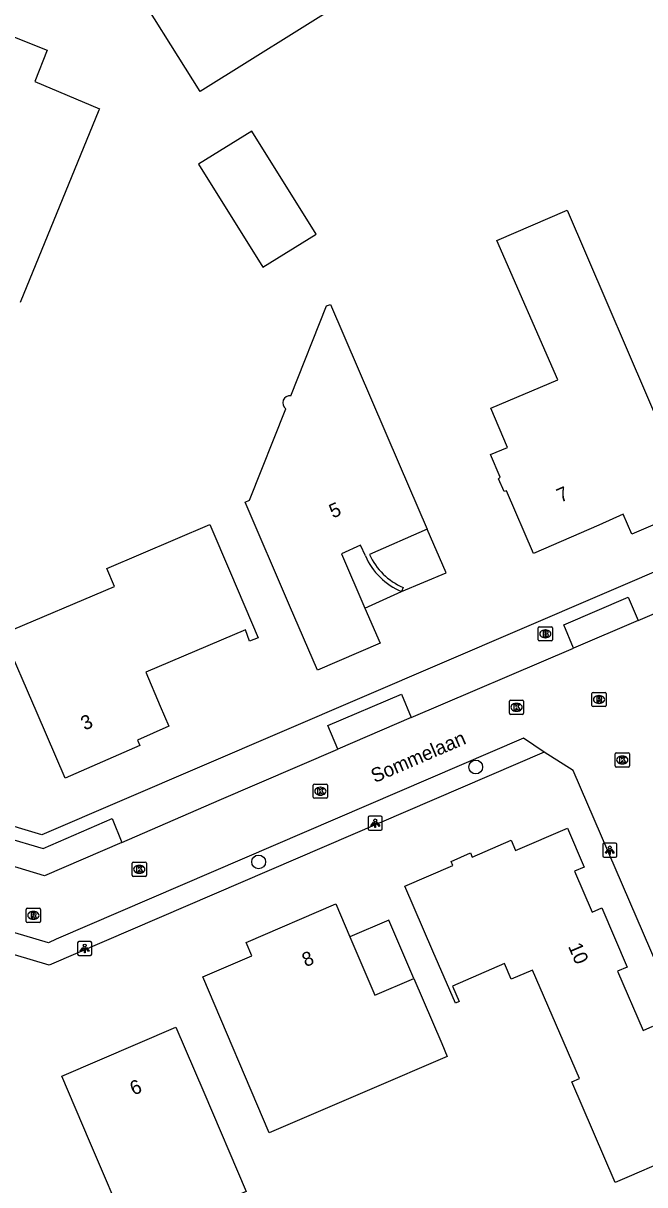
# Model space of a CAD drawing. Extents: x 157767 to 159171, y 387842 to 389425.
# Drawn here: x 158095.4 to 158139.4, y 388753.5 to 388835.7 of the extents above; entities that cross this region are included whole.
import ezdxf

# ---------------------------------------------------------------- set-up
doc = ezdxf.new("R2010")
doc.units = 0
for name, color, linetype in [('IMGEO_Boom', 7, 'Continuous'), ('IMGEO_Brandkraan', 7, 'Continuous'), ('IMGEO_Kolk', 7, 'Continuous'), ('IMGEO_Lichtpunt', 7, 'Continuous'), ('IMGEO_Openbare_ruimte_label', 7, 'Continuous'), ('IMGEO_Pand', 7, 'Continuous'), ('IMGEO_Pand_nummerreeks', 7, 'Continuous'), ('IMGEO_Pand_overbouw', 7, 'Continuous'), ('IMGEO_Rijbaan_lokaal_open', 7, 'Continuous'), ('IMGEO_Rioolput', 7, 'Continuous'), ('IMGEO_Voetpad_open', 7, 'Continuous')]:
    doc.layers.add(name, color=color, linetype=linetype)

msp = doc.modelspace()

# ---------------------------------------------------------------- linework, layer by layer
at = {"layer": 'IMGEO_Boom'}
for centre in [(158127.417, 388783.049), (158112.044, 388776.326)]:
    msp.add_circle(centre, 0.489, dxfattribs=at)
at = {"layer": 'IMGEO_Brandkraan'}
for p, q in [((158131.848, 388792.054), (158131.848, 388792.906)), ((158131.923, 388792.98), (158132.775, 388792.98)), ((158132.336, 388792.76), (158132.361, 388792.76)), ((158132.849, 388792.906), (158132.849, 388792.054)), ((158132.775, 388791.98), (158131.923, 388791.98)), ((158132.359, 388792.2), (158132.334, 388792.2))]:
    msp.add_line(p, q, dxfattribs=at)
for points in [[(158131.848, 388792.054), (158131.848, 388792.906)], [(158131.923, 388792.98), (158132.775, 388792.98)], [(158132.849, 388792.906), (158132.849, 388792.054)], [(158132.775, 388791.98), (158131.923, 388791.98)], [(158132.196, 388792.68), (158132.196, 388792.28), (158132.409, 388792.28)], [(158132.427, 388792.68), (158132.196, 388792.68)], [(158132.375, 388792.599), (158132.321, 388792.599), (158132.321, 388792.523)], [(158132.321, 388792.523), (158132.374, 388792.523)], [(158132.383, 388792.447), (158132.321, 388792.447), (158132.321, 388792.366)], [(158132.321, 388792.366), (158132.383, 388792.366)]]:
    msp.add_lwpolyline(points, dxfattribs=at)
for centre, radius, start, end in [((158131.925, 388792.904), 0.0765, 91.55205, 178.44795), ((158131.925, 388792.904), 0.0765, 91.55205, 178.44795), ((158132.773, 388792.904), 0.0765, 1.55205, 88.44795), ((158132.773, 388792.904), 0.0765, 1.55205, 88.44795), ((158131.925, 388792.056), 0.0765, 181.55205, 268.44795), ((158131.925, 388792.056), 0.0765, 181.55205, 268.44795), ((158132.376, 388792.561), 0.0379, 267.82845, 90.93552), ((158132.384, 388792.406), 0.0404, 269.87594, 90.50774), ((158132.415, 388792.531), 0.251, 268.66757, 293.53466), ((158132.431, 388792.535), 0.145, 59.4692, 91.53667), ((158132.456, 388792.582), 0.0922, 285.51372, 58.15012), ((158132.461, 388792.39), 0.105, 301.31148, 78.98903), ((158132.773, 388792.056), 0.0765, 271.55205, 358.44795), ((158132.773, 388792.056), 0.0765, 271.55205, 358.44795)]:
    msp.add_arc(centre, radius, start, end, dxfattribs=at)
for centre, major_axis, ratio, start_param, end_param in [((158132.335, 388792.48), (-0.387, 0.002), 0.722429, 4.712389, 7.853982), ((158132.36, 388792.48), (-0.39, 0.002), 0.717154, 1.570796, 4.712389)]:
    msp.add_ellipse(centre, major_axis=major_axis, ratio=ratio, start_param=start_param, end_param=end_param, dxfattribs=at)
at = {"layer": 'IMGEO_Kolk'}
for p, q in [((158129.81, 388786.853), (158129.81, 388787.705)), ((158129.885, 388787.779), (158130.737, 388787.779)), ((158130.321, 388786.999), (158130.296, 388786.999)), ((158130.298, 388787.559), (158130.323, 388787.559)), ((158130.811, 388787.705), (158130.811, 388786.853)), ((158130.737, 388786.779), (158129.885, 388786.779)), ((158137.3, 388783.122), (158137.3, 388783.974)), ((158137.375, 388784.048), (158138.227, 388784.048)), ((158137.788, 388783.828), (158137.813, 388783.828)), ((158138.301, 388783.974), (158138.301, 388783.122)), ((158138.227, 388783.048), (158137.375, 388783.048)), ((158137.811, 388783.268), (158137.786, 388783.268)), ((158115.916, 388780.91), (158115.916, 388781.762)), ((158115.991, 388781.836), (158116.843, 388781.836)), ((158116.404, 388781.616), (158116.429, 388781.616)), ((158116.917, 388781.762), (158116.917, 388780.91)), ((158116.843, 388780.836), (158115.991, 388780.836)), ((158116.427, 388781.056), (158116.402, 388781.056)), ((158103.166, 388776.305), (158104.018, 388776.305)), ((158103.091, 388775.379), (158103.091, 388776.231)), ((158103.602, 388775.525), (158103.577, 388775.525)), ((158103.579, 388776.085), (158103.604, 388776.085)), ((158104.092, 388776.231), (158104.092, 388775.379)), ((158104.018, 388775.305), (158103.166, 388775.305))]:
    msp.add_line(p, q, dxfattribs=at)
for points in [[(158129.81, 388786.853), (158129.81, 388787.705)], [(158129.885, 388787.779), (158130.737, 388787.779)], [(158130.131, 388787.479), (158130.254, 388787.479), (158130.254, 388787.328), (158130.384, 388787.479), (158130.548, 388787.479), (158130.402, 388787.328), (158130.555, 388787.079), (158130.403, 388787.079), (158130.318, 388787.243), (158130.254, 388787.176), (158130.254, 388787.079), (158130.131, 388787.079), (158130.131, 388787.479)], [(158130.811, 388787.705), (158130.811, 388786.853)], [(158130.737, 388786.779), (158129.885, 388786.779)], [(158137.3, 388783.122), (158137.3, 388783.974)], [(158137.375, 388784.048), (158138.227, 388784.048)], [(158137.621, 388783.748), (158137.744, 388783.748), (158137.744, 388783.597), (158137.874, 388783.748), (158138.038, 388783.748), (158137.892, 388783.597), (158138.045, 388783.348), (158137.893, 388783.348), (158137.808, 388783.512), (158137.744, 388783.445), (158137.744, 388783.348), (158137.621, 388783.348), (158137.621, 388783.748)], [(158138.301, 388783.974), (158138.301, 388783.122)], [(158138.227, 388783.048), (158137.375, 388783.048)], [(158115.916, 388780.91), (158115.916, 388781.762)], [(158115.991, 388781.836), (158116.843, 388781.836)], [(158116.237, 388781.536), (158116.36, 388781.536), (158116.36, 388781.385), (158116.49, 388781.536), (158116.654, 388781.536), (158116.508, 388781.385), (158116.661, 388781.136), (158116.509, 388781.136), (158116.424, 388781.3), (158116.36, 388781.233), (158116.36, 388781.136), (158116.237, 388781.136), (158116.237, 388781.536)], [(158116.917, 388781.762), (158116.917, 388780.91)], [(158116.843, 388780.836), (158115.991, 388780.836)], [(158103.166, 388776.305), (158104.018, 388776.305)], [(158103.091, 388775.379), (158103.091, 388776.231)], [(158103.412, 388776.005), (158103.535, 388776.005), (158103.535, 388775.854), (158103.665, 388776.005), (158103.829, 388776.005), (158103.683, 388775.854), (158103.836, 388775.605), (158103.684, 388775.605), (158103.599, 388775.769), (158103.535, 388775.702), (158103.535, 388775.605), (158103.412, 388775.605), (158103.412, 388776.005)], [(158104.092, 388776.231), (158104.092, 388775.379)], [(158104.018, 388775.305), (158103.166, 388775.305)]]:
    msp.add_lwpolyline(points, dxfattribs=at)
for centre, start, end in [((158129.887, 388787.703), 91.55205, 178.44795), ((158129.887, 388787.703), 91.55205, 178.44795), ((158130.735, 388787.703), 1.55205, 88.44795), ((158130.735, 388787.703), 1.55205, 88.44795), ((158129.887, 388786.855), 181.55205, 268.44795), ((158129.887, 388786.855), 181.55205, 268.44795), ((158130.735, 388786.855), 271.55205, 358.44795), ((158130.735, 388786.855), 271.55205, 358.44795), ((158137.377, 388783.972), 91.55205, 178.44795), ((158137.377, 388783.972), 91.55205, 178.44795), ((158138.225, 388783.972), 1.55205, 88.44795), ((158138.225, 388783.972), 1.55205, 88.44795), ((158137.377, 388783.124), 181.55205, 268.44795), ((158137.377, 388783.124), 181.55205, 268.44795), ((158138.225, 388783.124), 271.55205, 358.44795), ((158138.225, 388783.124), 271.55205, 358.44795), ((158115.993, 388781.76), 91.55205, 178.44795), ((158115.993, 388781.76), 91.55205, 178.44795), ((158116.841, 388781.76), 1.55205, 88.44795), ((158116.841, 388781.76), 1.55205, 88.44795), ((158115.993, 388780.912), 181.55205, 268.44795), ((158115.993, 388780.912), 181.55205, 268.44795), ((158116.841, 388780.912), 271.55205, 358.44795), ((158116.841, 388780.912), 271.55205, 358.44795), ((158103.168, 388776.229), 91.55205, 178.44795), ((158103.168, 388776.229), 91.55205, 178.44795), ((158104.016, 388776.229), 1.55205, 88.44795), ((158104.016, 388776.229), 1.55205, 88.44795), ((158103.168, 388775.381), 181.55205, 268.44795), ((158103.168, 388775.381), 181.55205, 268.44795), ((158104.016, 388775.381), 271.55205, 358.44795), ((158104.016, 388775.381), 271.55205, 358.44795)]:
    msp.add_arc(centre, 0.0765, start, end, dxfattribs=at)
for centre, major_axis, ratio, start_param, end_param in [((158130.297, 388787.279), (-0.387, 0.002), 0.722429, 4.712389, 7.853982), ((158130.322, 388787.279), (-0.39, 0.002), 0.717154, 1.570796, 4.712389), ((158137.787, 388783.548), (-0.387, 0.002), 0.722429, 4.712389, 7.853982), ((158137.812, 388783.548), (-0.39, 0.002), 0.717154, 1.570796, 4.712389), ((158116.403, 388781.336), (-0.387, 0.002), 0.722429, 4.712389, 7.853982), ((158116.428, 388781.336), (-0.39, 0.002), 0.717154, 1.570796, 4.712389), ((158103.578, 388775.805), (-0.387, 0.002), 0.722429, 4.712389, 7.853982), ((158103.603, 388775.805), (-0.39, 0.002), 0.717154, 1.570796, 4.712389)]:
    msp.add_ellipse(centre, major_axis=major_axis, ratio=ratio, start_param=start_param, end_param=end_param, dxfattribs=at)
at = {"layer": 'IMGEO_Lichtpunt'}
for p, q in [((158120.707, 388779.569), (158119.899, 388779.569)), ((158120.707, 388779.569), (158119.899, 388779.569)), ((158119.805, 388779.474), (158119.805, 388778.667)), ((158119.805, 388779.474), (158119.805, 388778.667)), ((158120.801, 388778.667), (158120.801, 388779.474)), ((158120.801, 388778.667), (158120.801, 388779.474)), ((158119.899, 388778.573), (158120.707, 388778.573)), ((158119.899, 388778.573), (158120.707, 388778.573)), ((158136.414, 388777.561), (158136.414, 388776.754)), ((158136.414, 388777.561), (158136.414, 388776.754)), ((158137.316, 388777.656), (158136.508, 388777.656)), ((158137.316, 388777.656), (158136.508, 388777.656)), ((158137.41, 388776.754), (158137.41, 388777.561)), ((158137.41, 388776.754), (158137.41, 388777.561)), ((158136.508, 388776.66), (158137.316, 388776.66)), ((158136.508, 388776.66), (158137.316, 388776.66)), ((158099.224, 388770.601), (158099.224, 388769.794)), ((158099.224, 388770.601), (158099.224, 388769.794)), ((158100.126, 388770.696), (158099.318, 388770.696)), ((158100.126, 388770.696), (158099.318, 388770.696)), ((158100.22, 388769.794), (158100.22, 388770.601)), ((158100.22, 388769.794), (158100.22, 388770.601)), ((158099.318, 388769.7), (158100.126, 388769.7)), ((158099.318, 388769.7), (158100.126, 388769.7))]:
    msp.add_line(p, q, dxfattribs=at)
for points in [[(158120.179, 388779.138), (158120.218, 388779.11), (158120.03, 388778.848), (158119.992, 388778.875), (158120.179, 388779.138)], [(158120.281, 388779.09), (158120.328, 388779.09), (158120.328, 388778.768), (158120.281, 388778.768), (158120.281, 388779.09)], [(158120.391, 388779.11), (158120.429, 388779.137), (158120.616, 388778.875), (158120.577, 388778.847), (158120.391, 388779.11)], [(158136.788, 388777.225), (158136.827, 388777.197), (158136.639, 388776.935), (158136.601, 388776.962), (158136.788, 388777.225)], [(158136.89, 388777.177), (158136.937, 388777.177), (158136.937, 388776.855), (158136.89, 388776.855), (158136.89, 388777.177)], [(158137, 388777.197), (158137.038, 388777.224), (158137.225, 388776.962), (158137.186, 388776.934), (158137, 388777.197)], [(158099.598, 388770.265), (158099.637, 388770.237), (158099.449, 388769.975), (158099.411, 388770.002), (158099.598, 388770.265)], [(158099.7, 388770.217), (158099.747, 388770.217), (158099.747, 388769.895), (158099.7, 388769.895), (158099.7, 388770.217)], [(158099.81, 388770.237), (158099.848, 388770.264), (158100.035, 388770.002), (158099.996, 388769.974), (158099.81, 388770.237)]]:
    msp.add_lwpolyline(points, dxfattribs=at)
for centre in [(158120.304, 388779.272), (158136.913, 388777.359), (158099.723, 388770.399)]:
    msp.add_circle(centre, 0.0994, dxfattribs=at)
for centre, start, end in [((158119.899, 388779.474), 90, 180), ((158119.899, 388779.474), 90, 180), ((158120.707, 388779.474), 0, 90), ((158120.707, 388779.474), 0, 90), ((158119.899, 388778.667), 180, 270), ((158119.899, 388778.667), 180, 270), ((158120.707, 388778.667), 270, 0), ((158120.707, 388778.667), 270, 360), ((158136.508, 388777.561), 90, 180), ((158136.508, 388777.561), 90, 180), ((158137.316, 388777.561), 0, 90), ((158137.316, 388777.561), 0, 90), ((158136.508, 388776.754), 180, 270), ((158136.508, 388776.754), 180, 270), ((158137.316, 388776.754), 270, 0), ((158137.316, 388776.754), 270, 360), ((158099.318, 388770.601), 90, 180), ((158099.318, 388770.601), 90, 180), ((158100.126, 388770.601), 0, 90), ((158100.126, 388770.601), 0, 90), ((158099.318, 388769.794), 180, 270), ((158099.318, 388769.794), 180, 270), ((158100.126, 388769.794), 270, 0), ((158100.126, 388769.794), 270, 360)]:
    msp.add_arc(centre, 0.0946, start, end, dxfattribs=at)
at = {"layer": 'IMGEO_Pand'}
for points in [[(158107.9, 388830.88), (158102.6, 388839.361), (158099.95, 388843.6), (158104.286, 388846.313), (158104.628, 388845.765), (158106.324, 388846.828), (158105.97, 388847.367), (158110.29, 388850.07), (158112.945, 388845.833), (158118.26, 388837.349), (158107.9, 388830.88)], [(158090.94, 388832.057), (158092.413, 388835.668), (158097.058, 388833.817), (158096.185, 388831.597), (158100.769, 388829.656), (158100.729, 388829.559), (158095.153, 388815.955)], [(158107.791, 388825.731), (158112.347, 388818.441), (158116.114, 388820.795), (158111.558, 388828.085), (158107.791, 388825.731)], [(158133.899, 388822.494), (158140.955, 388806.047), (158142.926, 388801.451), (158138.474, 388799.53), (158137.864, 388800.944), (158136.133, 388800.188), (158131.502, 388798.164), (158129.587, 388802.604), (158129.432, 388802.561), (158129.037, 388803.465), (158129.142, 388803.58), (158128.469, 388805.175), (158129.667, 388805.684), (158128.486, 388808.465), (158133.228, 388810.479), (158128.925, 388820.345), (158133.899, 388822.494)], [(158114.326, 388809.33), (158116.857, 388815.698), (158117.129, 388815.797), (158122.003, 388804.491)], [(158119.603, 388797.997), (158119.263, 388798.752), (158117.903, 388798.148), (158119.569, 388794.299), (158120.642, 388791.821), (158116.209, 388789.896), (158114.234, 388794.49), (158111.093, 388801.795), (158111.389, 388801.957), (158113.969, 388808.421)], [(158122.003, 388804.491), (158123.983, 388799.899), (158119.901, 388798.11)], [(158112.009, 388792.192), (158111.402, 388791.962), (158111.102, 388792.762), (158104.047, 388789.771), (158105.08, 388787.353), (158105.683, 388785.942), (158103.459, 388784.961), (158103.62, 388784.578), (158098.336, 388782.268), (158096.353, 388786.858), (158093.926, 388792.476), (158101.828, 388795.84), (158101.291, 388797.104), (158108.593, 388800.213), (158110.05, 388796.793), (158112.009, 388792.192)], [(158122.274, 388795.764), (158122.168, 388795.47)], [(158124.388, 388770.019), (158122.403, 388774.608), (158125.802, 388776.074), (158125.676, 388776.368), (158127.043, 388776.961), (158127.17, 388776.668), (158129.923, 388777.86), (158130.241, 388777.127), (158133.91, 388778.716), (158135.096, 388775.965), (158134.408, 388775.669), (158135.654, 388772.776), (158136.342, 388773.072), (158138.148, 388768.88), (158137.461, 388768.583), (158139.269, 388764.39), (158139.953, 388764.685)], [(158119.894, 388760.181), (158112.797, 388757.131), (158108.08, 388768.184), (158111.563, 388769.67), (158111.158, 388770.62), (158117.502, 388773.351), (158118.506, 388771.013), (158120.279, 388766.885), (158123.034, 388768.068), (158125.008, 388763.474), (158125.405, 388762.549), (158119.894, 388760.181)], [(158142.873, 388756.025), (158138.284, 388754.042), (158137.304, 388753.618), (158134.219, 388760.754), (158134.76, 388760.988), (158131.438, 388768.674), (158129.935, 388768.024), (158129.459, 388769.127), (158125.779, 388767.536), (158126.255, 388766.434), (158125.988, 388766.318), (158124.388, 388770.019)], [(158102.873, 388750), (158100.069, 388756.563), (158098.104, 388761.16), (158106.19, 388764.627), (158108.155, 388760.03), (158111.161, 388752.999), (158104.146, 388750), (158103.07, 388749.54), (158102.873, 388750)]]:
    msp.add_lwpolyline(points, dxfattribs=at)
for centre, radius, start, end in [((158114.253, 388808.834), 0.501, 81.58702, 235.52921), ((158124.06, 388799.956), 4.869, 203.72685, 247.1283), ((158124.069, 388799.952), 4.557, 203.84964, 246.806)]:
    msp.add_arc(centre, radius, start, end, dxfattribs=at)
at = {"layer": 'IMGEO_Pand_overbouw'}
for points in [[(158122.168, 388795.47), (158125.323, 388796.79), (158123.983, 388799.899), (158119.901, 388798.11)], [(158119.603, 388797.997), (158119.263, 388798.752), (158117.903, 388798.148), (158119.569, 388794.299)], [(158119.569, 388794.299), (158122.168, 388795.47)], [(158122.274, 388795.764), (158122.168, 388795.47)]]:
    msp.add_lwpolyline(points, dxfattribs=at)
msp.add_lwpolyline([(158123.034, 388768.068), (158121.261, 388772.197), (158118.506, 388771.013), (158120.279, 388766.885)], close=True, dxfattribs=at)
for centre, radius, start, end in [((158124.06, 388799.956), 4.869, 203.72685, 247.1283), ((158124.069, 388799.952), 4.557, 203.84964, 246.806)]:
    msp.add_arc(centre, radius, start, end, dxfattribs=at)
at = {"layer": 'IMGEO_Rijbaan_lokaal_open'}
for points in [[(158138.917, 388793.421), (158149.891, 388798.147)], [(158138.917, 388793.421), (158134.35, 388791.467)], [(158122.856, 388786.566), (158134.35, 388791.467)], [(158122.856, 388786.566), (158117.651, 388784.313)], [(158132.266, 388784.089), (158130.812, 388785.098), (158097.692, 388770.854), (158097.152, 388770.606), (158071.312, 388778.281)], [(158102.35, 388777.71), (158109.251, 388780.697), (158117.651, 388784.313)], [(158155.532, 388728.793), (158156.474, 388731.409), (158148.476, 388750), (158147.334, 388752.654), (158134.314, 388782.791), (158132.266, 388784.089)], [(158102.35, 388777.71), (158096.873, 388775.34), (158090.794, 388777.174)]]:
    msp.add_lwpolyline(points, dxfattribs=at)
at = {"layer": 'IMGEO_Rioolput'}
for p, q in [((158135.652, 388787.404), (158135.652, 388788.256)), ((158135.727, 388788.33), (158136.579, 388788.33)), ((158136.14, 388788.11), (158136.165, 388788.11)), ((158136.653, 388788.256), (158136.653, 388787.404)), ((158136.579, 388787.33), (158135.727, 388787.33)), ((158136.163, 388787.55), (158136.138, 388787.55)), ((158095.663, 388773.044), (158096.515, 388773.044)), ((158095.588, 388772.118), (158095.588, 388772.97)), ((158096.099, 388772.264), (158096.074, 388772.264)), ((158096.076, 388772.824), (158096.101, 388772.824)), ((158096.589, 388772.97), (158096.589, 388772.118)), ((158096.515, 388772.044), (158095.663, 388772.044))]:
    msp.add_line(p, q, dxfattribs=at)
for points in [[(158135.652, 388787.404), (158135.652, 388788.256)], [(158135.727, 388788.33), (158136.579, 388788.33)], [(158136.241, 388788.028), (158135.989, 388788.03), (158135.989, 388787.63)], [(158135.989, 388787.63), (158136.113, 388787.63), (158136.113, 388787.792), (158136.124, 388787.792)], [(158136.167, 388787.949), (158136.113, 388787.949), (158136.113, 388787.868)], [(158136.113, 388787.868), (158136.165, 388787.868)], [(158136.653, 388788.256), (158136.653, 388787.404)], [(158136.579, 388787.33), (158135.727, 388787.33)], [(158136.171, 388787.763), (158136.242, 388787.63), (158136.382, 388787.63), (158136.317, 388787.756)], [(158095.663, 388773.044), (158096.515, 388773.044)], [(158095.588, 388772.118), (158095.588, 388772.97)], [(158096.177, 388772.742), (158095.925, 388772.744), (158095.925, 388772.344)], [(158095.925, 388772.344), (158096.049, 388772.344), (158096.049, 388772.506), (158096.06, 388772.506)], [(158096.103, 388772.663), (158096.049, 388772.663), (158096.049, 388772.582)], [(158096.049, 388772.582), (158096.101, 388772.582)], [(158096.107, 388772.477), (158096.178, 388772.344), (158096.318, 388772.344), (158096.253, 388772.47)], [(158096.589, 388772.97), (158096.589, 388772.118)], [(158096.515, 388772.044), (158095.663, 388772.044)]]:
    msp.add_lwpolyline(points, dxfattribs=at)
for centre, radius, start, end in [((158135.729, 388788.254), 0.0765, 91.55205, 178.44795), ((158135.729, 388788.254), 0.0765, 91.55205, 178.44795), ((158136.123, 388787.739), 0.0533, 26.02933, 88.69889), ((158136.149, 388788.057), 0.19, 274.7715, 282.96867), ((158136.173, 388787.853), 0.0964, 77.00612, 93.18647), ((158136.187, 388787.91), 0.0378, 276.66336, 79.67722), ((158136.24, 388787.918), 0.109, 350.36119, 89.41601), ((158136.238, 388787.918), 0.112, 277.58423, 350.98172), ((158136.222, 388787.703), 0.108, 29.51342, 73.79051), ((158136.577, 388788.254), 0.0765, 1.55205, 88.44795), ((158136.577, 388788.254), 0.0765, 1.55205, 88.44795), ((158135.729, 388787.406), 0.0765, 181.55205, 268.44795), ((158135.729, 388787.406), 0.0765, 181.55205, 268.44795), ((158136.577, 388787.406), 0.0765, 271.55205, 358.44795), ((158136.577, 388787.406), 0.0765, 271.55205, 358.44795), ((158095.665, 388772.968), 0.0765, 91.55205, 178.44795), ((158095.665, 388772.968), 0.0765, 91.55205, 178.44795), ((158096.513, 388772.968), 0.0765, 1.55205, 88.44795), ((158096.513, 388772.968), 0.0765, 1.55205, 88.44795), ((158096.059, 388772.453), 0.0533, 26.02933, 88.69889), ((158096.085, 388772.771), 0.19, 274.7715, 282.96867), ((158096.109, 388772.567), 0.0964, 77.00612, 93.18647), ((158096.123, 388772.624), 0.0378, 276.66336, 79.67722), ((158096.176, 388772.632), 0.109, 350.36119, 89.41601), ((158096.174, 388772.632), 0.112, 277.58423, 350.98172), ((158096.158, 388772.417), 0.108, 29.51342, 73.79051), ((158095.665, 388772.12), 0.0765, 181.55205, 268.44795), ((158095.665, 388772.12), 0.0765, 181.55205, 268.44795), ((158096.513, 388772.12), 0.0765, 271.55205, 358.44795), ((158096.513, 388772.12), 0.0765, 271.55205, 358.44795)]:
    msp.add_arc(centre, radius, start, end, dxfattribs=at)
for centre, major_axis, ratio, start_param, end_param in [((158136.139, 388787.83), (-0.387, 0.002), 0.722429, 4.712389, 7.853982), ((158136.164, 388787.83), (-0.39, 0.002), 0.717154, 1.570796, 4.712389), ((158096.075, 388772.544), (-0.387, 0.002), 0.722429, 4.712389, 7.853982), ((158096.1, 388772.544), (-0.39, 0.002), 0.717154, 1.570796, 4.712389)]:
    msp.add_ellipse(centre, major_axis=major_axis, ratio=ratio, start_param=start_param, end_param=end_param, dxfattribs=at)
at = {"layer": 'IMGEO_Voetpad_open'}
for points in [[(158183.864, 388823.28), (158161.367, 388806.591), (158159.023, 388804.985), (158096.685, 388778.239), (158072.557, 388785.494)], [(158134.35, 388791.467), (158133.661, 388793.113), (158138.212, 388795.082), (158138.917, 388793.421)], [(158117.651, 388784.313), (158116.934, 388785.981), (158122.171, 388788.217), (158122.856, 388786.566)], [(158132.266, 388784.089), (158097.205, 388769.015), (158070.254, 388777.047)], [(158090.794, 388777.174), (158091.318, 388778.876), (158096.777, 388777.279), (158101.66, 388779.393), (158102.35, 388777.71)]]:
    msp.add_lwpolyline(points, dxfattribs=at)

# ---------------------------------------------------------------- texts
at = {"layer": 'IMGEO_Openbare_ruimte_label'}
msp.add_text('Sommelaan', height=1, rotation=23.25876, dxfattribs=at).set_placement((158120.261, 388781.904))
at = {"layer": 'IMGEO_Pand_nummerreeks'}
for s, rotation, p in [('7', 23.60386, (158133.422, 388801.753)), ('5', 23.94685, (158117.309, 388800.641)), ('3', 23.61345, (158099.716, 388785.622)), ('10', 293.30737, (158133.943, 388770.352)), ('8', 23.29073, (158115.378, 388768.865)), ('6', 23.208, (158103.187, 388759.77))]:
    msp.add_text(s, height=1, rotation=rotation, dxfattribs=at).set_placement(p)

doc.saveas('drawing.dxf')
